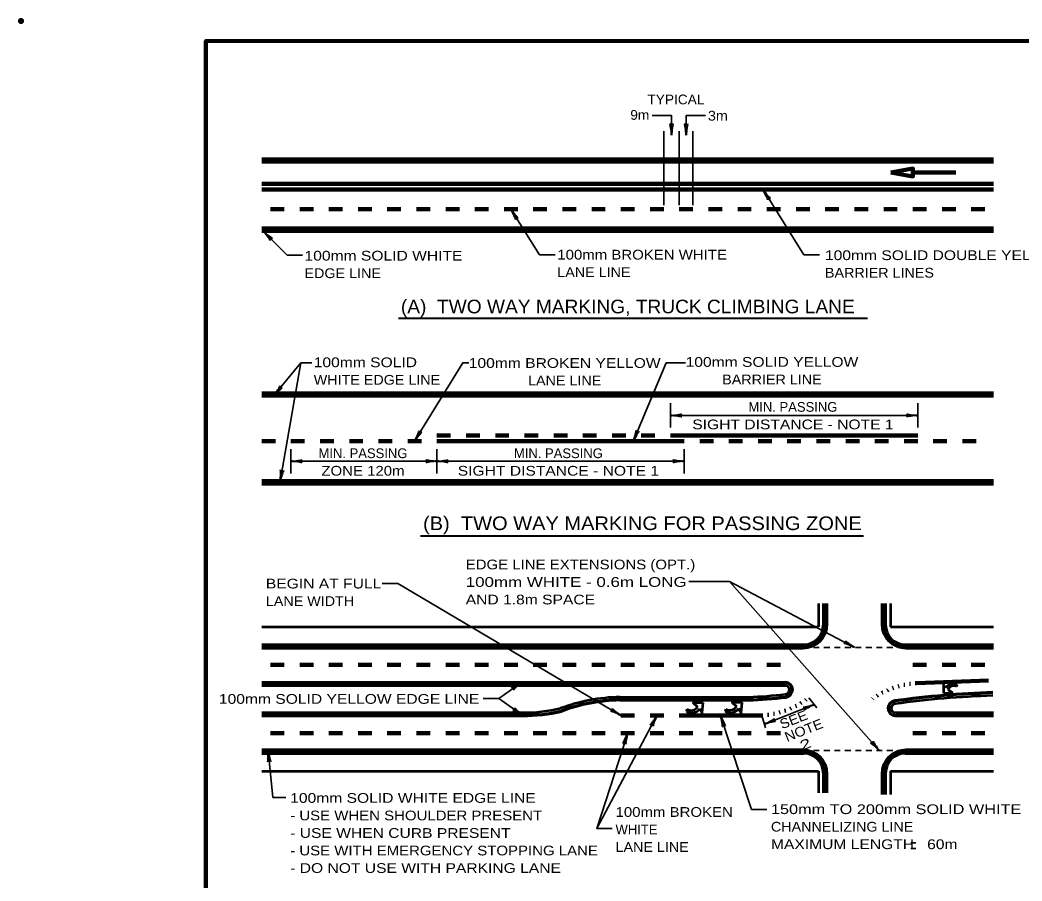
# Model space of a CAD drawing. Extents: x -90 to 765, y -1136 to -592.
# Drawn here: x -90.2 to 218.6, y -857.1 to -591.7 of the extents above; entities that cross this region are included whole.
import ezdxf
from ezdxf.enums import TextEntityAlignment as Align

# ---------------------------------------------------------------- set-up
doc = ezdxf.new("R2010")
doc.units = 0
doc.header["$LTSCALE"] = 1.2
doc.header["$PDMODE"] = 32
doc.header["$PDSIZE"] = 0.6
doc.linetypes.add('DOTTED', pattern=[1.5, 0.3, -1.2])
doc.linetypes.add('SHORT_DASHED', pattern=[2.7, 1.5, -1.2])
doc.layers.add('1', color=7, linetype='Continuous', lineweight=90)

msp = doc.modelspace()

# ---------------------------------------------------------------- linework, layer by layer
at = {"layer": '1', "lineweight": 35}
for p, q in [((108.194, -648.749), (108.194, -625.949)), ((112.994, -648.749), (112.994, -625.949)), ((117.194, -648.749), (117.194, -625.949)), ((-3.637, -697.37), (-0.31, -697.37)), ((110.294, -717.318), (110.294, -709.818)), ((186.494, -717.318), (186.494, -709.818)), ((110.294, -713.568), (186.494, -713.568)), ((-6.706, -723.918), (-6.706, -731.418)), ((38.294, -723.918), (38.294, -731.418)), ((114.494, -723.918), (114.494, -731.418)), ((115.938, -764.734), (128.515, -764.734)), ((57.322, -800.819), (64.765, -806.065)), ((139.244, -808.72), (154.603, -802.668)), ((152.905, -800.57), (155.395, -803.646)), ((125.716, -806.065), (135.211, -835.06)), ((138.438, -806.065), (139.594, -809.872)), ((-13.725, -816.856), (-12.315, -831.317)), ((-12.315, -831.317), (-8.296, -831.317)), ((135.211, -835.06), (140.011, -835.06)), ((87.549, -840.863), (92.28, -840.863))]:
    msp.add_line(p, q, dxfattribs=at)
at = {"layer": '1', "lineweight": 53}
for p, q in [((-15.706, -634.349), (209.894, -634.349)), ((-15.706, -656.849), (209.894, -656.849)), ((-15.706, -706.518), (209.894, -706.518)), ((-15.706, -734.718), (209.894, -734.718)), ((155.894, -771.565), (155.894, -778.765)), ((157.394, -771.565), (157.394, -778.165)), ((176.594, -771.565), (176.594, -778.165)), ((178.094, -771.565), (178.094, -778.765)), ((-15.706, -778.765), (155.894, -778.765)), ((178.094, -778.765), (209.894, -778.765)), ((-15.706, -784.165), (151.394, -784.165)), ((182.594, -784.165), (209.894, -784.165)), ((-15.706, -796.765), (145.715, -796.765)), ((198.567, -797.067), (198.645, -796.502)), ((94.694, -800.365), (134.294, -800.365)), ((-15.706, -805.165), (64.694, -805.165)), ((115.336, -804.126), (115.179, -804.772)), ((127.326, -804.056), (127.169, -804.702)), ((179.602, -805.165), (209.894, -805.165)), ((-15.706, -817.765), (151.394, -817.765)), ((182.594, -817.765), (209.894, -817.765)), ((-15.706, -823.165), (155.894, -823.165)), ((155.894, -823.165), (155.894, -829.868)), ((157.394, -823.765), (157.394, -829.868)), ((176.594, -823.765), (176.594, -830.365)), ((178.094, -823.165), (178.094, -830.365)), ((178.094, -823.165), (209.894, -823.165))]:
    msp.add_line(p, q, dxfattribs=at)
at = {"layer": '1'}
for p, q in [((-15.706, -635.249), (209.894, -635.249)), ((184.994, -638.699), (198.194, -638.699)), ((-15.706, -642.149), (209.894, -642.149)), ((-15.706, -643.949), (209.894, -643.949)), ((-13.006, -649.949), (-8.806, -649.949)), ((-4.006, -649.949), (0.194, -649.949)), ((4.994, -649.949), (9.194, -649.949)), ((13.994, -649.949), (18.194, -649.949)), ((22.994, -649.949), (27.194, -649.949)), ((31.994, -649.949), (36.194, -649.949)), ((40.994, -649.949), (45.194, -649.949)), ((49.994, -649.949), (54.194, -649.949)), ((58.994, -649.949), (63.194, -649.949)), ((67.994, -649.949), (72.194, -649.949)), ((76.994, -649.949), (81.194, -649.949)), ((85.994, -649.949), (90.194, -649.949)), ((94.994, -649.949), (99.194, -649.949)), ((103.994, -649.949), (108.194, -649.949)), ((112.994, -649.949), (117.194, -649.949)), ((121.994, -649.949), (126.194, -649.949)), ((130.994, -649.949), (135.194, -649.949)), ((139.994, -649.949), (144.194, -649.949)), ((148.994, -649.949), (153.194, -649.949)), ((157.994, -649.949), (162.194, -649.949)), ((166.994, -649.949), (171.194, -649.949)), ((175.994, -649.949), (180.194, -649.949)), ((184.994, -649.949), (189.194, -649.949)), ((193.994, -649.949), (198.194, -649.949)), ((202.994, -649.949), (207.194, -649.949)), ((-15.706, -655.949), (209.894, -655.949)), ((-15.706, -707.418), (209.894, -707.418)), ((-15.706, -721.518), (-11.506, -721.518)), ((-6.706, -721.518), (-2.506, -721.518)), ((2.294, -721.518), (6.494, -721.518)), ((11.294, -721.518), (15.494, -721.518)), ((20.294, -721.518), (24.494, -721.518)), ((29.294, -721.518), (33.494, -721.518)), ((38.294, -719.718), (42.494, -719.718)), ((38.294, -721.518), (114.494, -721.518)), ((47.294, -719.718), (51.494, -719.718)), ((56.294, -719.718), (60.494, -719.718)), ((65.294, -719.718), (69.494, -719.718)), ((74.294, -719.718), (78.494, -719.718)), ((83.294, -719.718), (87.494, -719.718)), ((92.294, -719.718), (96.494, -719.718)), ((101.294, -719.718), (105.494, -719.718)), ((110.294, -719.718), (186.494, -719.718)), ((119.294, -721.518), (123.494, -721.518)), ((128.294, -721.518), (132.494, -721.518)), ((137.294, -721.518), (141.494, -721.518)), ((146.294, -721.518), (150.494, -721.518)), ((155.294, -721.518), (159.494, -721.518)), ((164.294, -721.518), (168.494, -721.518)), ((173.294, -721.518), (177.494, -721.518)), ((182.294, -721.518), (186.494, -721.518)), ((191.294, -721.518), (195.494, -721.518)), ((200.294, -721.518), (204.494, -721.518)), ((-15.706, -733.818), (209.894, -733.818)), ((158.294, -771.565), (158.294, -777.865)), ((175.694, -771.565), (175.694, -777.865)), ((-15.706, -785.065), (151.094, -785.065)), ((182.894, -785.065), (209.894, -785.065)), ((-13.006, -790.465), (-8.806, -790.465)), ((-4.006, -790.465), (0.194, -790.465)), ((4.994, -790.465), (9.194, -790.465)), ((13.994, -790.465), (18.194, -790.465)), ((22.994, -790.465), (27.194, -790.465)), ((31.994, -790.465), (36.194, -790.465)), ((40.994, -790.465), (45.194, -790.465)), ((49.994, -790.465), (54.194, -790.465)), ((58.994, -790.465), (63.194, -790.465)), ((67.994, -790.465), (72.194, -790.465)), ((76.994, -790.465), (81.194, -790.465)), ((85.994, -790.465), (90.194, -790.465)), ((94.994, -790.465), (99.194, -790.465)), ((103.994, -790.465), (108.194, -790.465)), ((112.994, -790.465), (117.194, -790.465)), ((121.994, -790.465), (126.194, -790.465)), ((130.994, -790.465), (135.194, -790.465)), ((139.994, -790.465), (144.194, -790.465)), ((184.994, -790.465), (189.194, -790.465)), ((193.994, -790.465), (198.194, -790.465)), ((202.994, -790.465), (207.194, -790.465)), ((186.095, -796.077), (208.345, -795.288)), ((94.994, -806.065), (99.194, -806.065)), ((103.994, -806.065), (108.194, -806.065)), ((112.994, -806.065), (138.438, -806.065)), ((-13.006, -811.465), (-8.806, -811.465)), ((-4.006, -811.465), (0.194, -811.465)), ((4.994, -811.465), (9.194, -811.465)), ((13.994, -811.465), (18.194, -811.465)), ((22.994, -811.465), (27.194, -811.465)), ((31.994, -811.465), (36.194, -811.465)), ((40.994, -811.465), (45.194, -811.465)), ((49.994, -811.465), (54.194, -811.465)), ((58.994, -811.465), (63.194, -811.465)), ((67.994, -811.465), (72.194, -811.465)), ((76.994, -811.465), (81.194, -811.465)), ((85.994, -811.465), (90.194, -811.465)), ((94.994, -811.465), (99.194, -811.465)), ((103.994, -811.465), (108.194, -811.465)), ((112.994, -811.465), (117.194, -811.465)), ((121.994, -811.465), (126.194, -811.465)), ((130.994, -811.465), (135.194, -811.465)), ((139.994, -811.465), (144.194, -811.465)), ((184.994, -811.465), (189.194, -811.465)), ((193.994, -811.465), (198.194, -811.465)), ((202.994, -811.465), (207.194, -811.465)), ((-15.706, -816.865), (151.094, -816.865)), ((182.894, -816.865), (209.894, -816.865)), ((158.294, -824.065), (158.294, -829.868)), ((175.694, -824.065), (175.694, -830.365))]:
    msp.add_line(p, q, dxfattribs=at)
at = {"layer": '1', "lineweight": 40}
for p, q in [((26.444, -683.56), (171.056, -683.56)), ((33.209, -750.71), (169.778, -750.71))]:
    msp.add_line(p, q, dxfattribs=at)
at = {"layer": '1', "linetype": 'SHORT_DASHED', "lineweight": 35}
for p, q in [((151.094, -785.065), (182.894, -785.065)), ((151.094, -816.865), (182.894, -816.865))]:
    msp.add_line(p, q, dxfattribs=at)
at = {"layer": '1', "lineweight": 70}
for p, q in [((-15.706, -795.865), (145.715, -795.865)), ((94.694, -801.265), (134.294, -801.265)), ((-15.706, -806.065), (64.694, -806.065)), ((179.526, -806.065), (209.894, -806.065))]:
    msp.add_line(p, q, dxfattribs=at)
at = {"layer": '1', "lineweight": 158}
msp.add_lwpolyline([(758.78, -598.088), (-32.92, -598.188), (-32.82, -1124.188)], dxfattribs=at)
at = {"layer": '1', "lineweight": 35}
for points in [[(110.594, -627.149), (110.594, -621.149), (104.594, -621.149)], [(115.094, -627.149), (115.094, -621.149), (121.094, -621.149)], [(138.839, -643.949), (151.406, -664.013), (156.206, -664.013)], [(61.094, -649.949), (69.925, -664.049), (74.725, -664.049)], [(-15.186, -656.849), (-7.912, -664.122), (-3.112, -664.122)], [(-10.047, -733.818), (-3.637, -697.37), (-11.95, -707.418)], [(31.394, -721.518), (46.236, -697.37), (48.163, -697.37)], [(98.789, -721.548), (108.937, -697.37), (114.937, -697.37)], [(-6.706, -727.668), (38.294, -727.668), (114.494, -727.668)], [(21.442, -765.347), (26.242, -765.347), (94.994, -806.065)], [(166.994, -785.065), (128.515, -764.734), (174.648, -816.865)], [(52.522, -800.819), (57.322, -800.819), (64.35, -795.865)], [(97.094, -811.465), (87.549, -840.863), (106.094, -806.065)]]:
    msp.add_lwpolyline(points, dxfattribs=at)
at = {"layer": '1'}
msp.add_lwpolyline([(178.188, -638.699), (184.994, -639.899), (184.994, -637.499)], close=True, dxfattribs=at)
at = {"layer": '1', "lineweight": 53}
for points in [[(195.206, -797.524), (194.434, -796.51), (194.454, -799.202)], [(194.454, -799.202), (197.067, -798.93), (195.82, -798.032)], [(120.361, -802.132), (117.297, -802.141), (118.637, -803.33)], [(119.29, -803.991), (120.066, -805.258), (120.361, -802.132)], [(132.351, -802.062), (129.287, -802.071), (130.627, -803.26)], [(131.28, -803.921), (132.056, -805.188), (132.351, -802.062)]]:
    msp.add_lwpolyline(points, dxfattribs=at)
at = {"layer": '1'}
for centre, start, end in [((151.094, -777.865), 270, 0), ((182.894, -777.865), 180, 270), ((151.094, -824.065), 0, 90), ((182.894, -824.065), 90, 180)]:
    msp.add_arc(centre, 7.2, start, end, dxfattribs=at)
at = {"layer": '1', "lineweight": 53}
for centre, radius, start, end in [((151.394, -778.165), 6, 270, 0), ((182.594, -778.165), 6, 180, 270), ((145.611, -798.115), 1.352, 275.50285, 87.34859), ((197.447, -798.766), 2.561, 62.10089, 151.0021), ((130.168, -675.226), 125.207, 271.88819, 277.13284), ((219.529, -1094.063), 294.329, 91.91621, 97.80945), ((197.672, -798.912), 2.051, 64.13204, 154.56308), ((95.96, -857.195), 56.845, 91.29696, 110.144), ((179.63, -803.815), 1.352, 95.50285, 267.34859), ((65.107, -757.214), 47.953, 269.51539, 283.72008), ((116.836, -802.287), 2.987, 236.30972, 325.21093), ((116.592, -802.09), 2.392, 238.34087, 328.77191), ((128.826, -802.217), 2.987, 236.30972, 325.21093), ((128.582, -802.02), 2.392, 238.34087, 328.77191), ((151.394, -823.765), 6, 0, 90), ((182.594, -823.765), 6, 90, 180)]:
    msp.add_arc(centre, radius, start, end, dxfattribs=at)
at = {"layer": '1', "lineweight": 70}
for centre, radius, start, end in [((145.611, -798.115), 2.252, 275.50285, 87.34859), ((219.529, -1094.063), 295.229, 91.91621, 97.80945), ((95.96, -857.195), 55.945, 91.29696, 110.144), ((130.168, -675.226), 126.107, 271.88819, 277.13284), ((179.63, -803.815), 2.252, 95.50285, 267.34859), ((65.107, -757.214), 48.853, 269.51539, 283.72008)]:
    msp.add_arc(centre, radius, start, end, dxfattribs=at)
at = {"layer": '1', "linetype": 'DOTTED'}
for centre, start, end in [((187.821, -822.415), 93.75019, 125.33349), ((136.711, -779.727), 273.75019, 307.84593)]:
    msp.add_arc(centre, 26.394, start, end, dxfattribs=at)
at = {"layer": '1', "lineweight": 40}
for centre, major_axis, ratio, start_param, end_param in [((110.262, -625.84), (0.187, -2.143), 0.122415, 0.8963533, 3.1415927), ((110.262, -625.84), (0.187, -2.143), 0.122415, 0.8963533, 3.1415927), ((110.848, -625.804), (-0.211, -2.108), 0.07063, 3.1407148, 5.41811), ((110.848, -625.804), (-0.211, -2.108), 0.07063, 3.1407148, 5.41811), ((114.762, -625.84), (0.187, -2.143), 0.122415, 0.8963533, 3.1415927), ((115.348, -625.804), (-0.211, -2.108), 0.07063, 3.1407148, 5.41811), ((139.337, -645.223), (-0.94, 1.898), 0.07063, 3.1407148, 5.41811), ((139.815, -644.883), (-1.296, 1.717), 0.122415, 0.8963533, 3.1415927), ((61.592, -651.223), (-0.94, 1.898), 0.07063, 3.1407148, 5.41811), ((62.07, -650.883), (-1.296, 1.717), 0.122415, 0.8963533, 3.1415927), ((-14.414, -657.979), (-1.341, 1.639), 0.07063, 3.1407148, 5.41811), ((-14.025, -657.54), (-1.648, 1.383), 0.122415, 0.8963533, 3.1415927), ((-11.371, -706.198), (-1.222, -1.77), 0.122415, 0.8963533, 3.1415927), ((-11.371, -706.198), (-1.222, -1.77), 0.122415, 0.8963533, 3.1415927), ((-10.897, -706.544), (-1.506, -1.49), 0.07063, 3.1407148, 5.41811), ((-10.897, -706.544), (-1.506, -1.49), 0.07063, 3.1407148, 5.41811), ((111.603, -713.237), (-2.143, -0.187), 0.122415, 0.8963533, 3.1415927), ((111.603, -713.237), (-2.143, -0.187), 0.122415, 0.8963533, 3.1415927), ((185.149, -713.314), (2.108, -0.211), 0.07063, 3.1407148, 5.41811), ((185.149, -713.314), (2.108, -0.211), 0.07063, 3.1407148, 5.41811), ((111.638, -713.822), (-2.108, 0.211), 0.07063, 3.1407148, 5.41811), ((111.638, -713.822), (-2.108, 0.211), 0.07063, 3.1407148, 5.41811), ((185.184, -713.9), (2.143, 0.187), 0.122415, 0.8963533, 3.1415927), ((185.184, -713.9), (2.143, 0.187), 0.122415, 0.8963533, 3.1415927), ((31.797, -720.229), (-0.962, -1.924), 0.122415, 0.8963533, 3.1415927), ((31.797, -720.229), (-0.962, -1.924), 0.122415, 0.8963533, 3.1415927), ((32.314, -720.506), (-1.283, -1.685), 0.07063, 3.1407148, 5.41811), ((32.314, -720.506), (-1.283, -1.685), 0.07063, 3.1407148, 5.41811), ((98.99, -720.212), (-0.657, -2.048), 0.122415, 0.8963533, 3.1415927), ((99.544, -720.406), (-1.01, -1.862), 0.07063, 3.1407148, 5.41811), ((-5.362, -727.922), (-2.108, 0.211), 0.07063, 3.1407148, 5.41811), ((-5.362, -727.922), (-2.108, 0.211), 0.07063, 3.1407148, 5.41811), ((-5.397, -727.337), (-2.143, -0.187), 0.122415, 0.8963533, 3.1415927), ((-5.397, -727.337), (-2.143, -0.187), 0.122415, 0.8963533, 3.1415927), ((36.984, -728), (2.143, 0.187), 0.122415, 0.8963533, 3.1415927), ((36.949, -727.414), (2.108, -0.211), 0.07063, 3.1407148, 5.41811), ((39.638, -727.922), (-2.108, 0.211), 0.07063, 3.1407148, 5.41811), ((39.638, -727.922), (-2.108, 0.211), 0.07063, 3.1407148, 5.41811), ((39.603, -727.337), (-2.143, -0.187), 0.122415, 0.8963533, 3.1415927), ((39.603, -727.337), (-2.143, -0.187), 0.122415, 0.8963533, 3.1415927), ((113.184, -728), (2.143, 0.187), 0.122415, 0.8963533, 3.1415927), ((113.184, -728), (2.143, 0.187), 0.122415, 0.8963533, 3.1415927), ((113.149, -727.414), (2.108, -0.211), 0.07063, 3.1407148, 5.41811), ((113.149, -727.414), (2.108, -0.211), 0.07063, 3.1407148, 5.41811), ((-10.147, -732.471), (-0.187, -2.143), 0.122415, 0.8963533, 3.1415927), ((-10.147, -732.471), (-0.187, -2.143), 0.122415, 0.8963533, 3.1415927), ((-9.564, -732.538), (-0.573, -2.039), 0.07063, 3.1407148, 5.41811), ((-9.564, -732.538), (-0.573, -2.039), 0.07063, 3.1407148, 5.41811), ((165.681, -784.746), (1.982, -0.835), 0.122415, 0.8963533, 3.1415927), ((165.924, -784.212), (1.765, -1.171), 0.07063, 3.1407148, 5.41811), ((63.105, -796.432), (1.844, 1.042), 0.07063, 3.1407148, 5.41811), ((63.105, -796.432), (1.844, 1.042), 0.07063, 3.1407148, 5.41811), ((63.471, -796.89), (1.643, 1.388), 0.122415, 0.8963533, 3.1415927), ((63.471, -796.89), (1.643, 1.388), 0.122415, 0.8963533, 3.1415927), ((153.259, -802.925), (2.038, 0.577), 0.07063, 3.1407148, 5.41811), ((153.507, -803.456), (1.925, 0.96), 0.122415, 0.8963533, 3.1415927), ((63.504, -805.581), (1.859, -1.081), 0.122415, 0.8963533, 3.1415927), ((63.812, -805.083), (1.601, -1.387), 0.07063, 3.1407148, 5.41811), ((93.698, -805.683), (1.939, -0.931), 0.122415, 0.8963533, 3.1415927), ((93.966, -805.161), (1.706, -1.255), 0.07063, 3.1407148, 5.41811), ((105.237, -807.132), (1.177, 1.761), 0.07063, 3.1407148, 5.41811), ((105.237, -807.132), (1.177, 1.761), 0.07063, 3.1407148, 5.41811), ((105.771, -807.376), (0.842, 1.979), 0.122415, 0.8963533, 3.1415927), ((105.771, -807.376), (0.842, 1.979), 0.122415, 0.8963533, 3.1415927), ((125.893, -807.422), (-0.456, 2.069), 0.07063, 3.1407148, 5.41811), ((125.893, -807.422), (-0.456, 2.069), 0.07063, 3.1407148, 5.41811), ((126.438, -807.206), (-0.845, 1.978), 0.122415, 0.8963533, 3.1415927), ((126.438, -807.206), (-0.845, 1.978), 0.122415, 0.8963533, 3.1415927), ((140.341, -807.932), (-1.925, -0.96), 0.122415, 0.8963533, 3.1415927), ((140.341, -807.932), (-1.925, -0.96), 0.122415, 0.8963533, 3.1415927), ((140.588, -808.464), (-2.038, -0.577), 0.07063, 3.1407148, 5.41811), ((140.588, -808.464), (-2.038, -0.577), 0.07063, 3.1407148, 5.41811), ((96.437, -812.665), (0.851, 1.94), 0.07063, 3.1407148, 5.41811), ((97.005, -812.813), (0.484, 2.096), 0.122415, 0.8963533, 3.1415927), ((173.532, -816.104), (1.56, -1.481), 0.122415, 0.8963533, 3.1415927), ((173.532, -816.104), (1.56, -1.481), 0.122415, 0.8963533, 3.1415927), ((173.947, -815.69), (1.239, -1.718), 0.07063, 3.1407148, 5.41811), ((173.947, -815.69), (1.239, -1.718), 0.07063, 3.1407148, 5.41811), ((-13.847, -818.219), (0.005, 2.118), 0.07063, 3.1407148, 5.41811), ((-13.268, -818.127), (-0.395, 2.115), 0.122415, 0.8963533, 3.1415927)]:
    msp.add_ellipse(centre, major_axis=major_axis, ratio=ratio, start_param=start_param, end_param=end_param, dxfattribs=at)
at = {"layer": '1'}
msp.add_point((-89.92, -591.988), dxfattribs=at)

# ---------------------------------------------------------------- texts
for s, height, width, p in [('TYPICAL', 3, 1.05, (103.175, -617.663)), ('9m', 3, 1.05, (97.888, -622.428)), ('3m', 3, 1.1, (121.821, -622.678)), ('100mm SOLID WHITE', 3, 1.2, (-2.53, -665.829)), ('100mm BROKEN WHITE', 3, 1.15, (75.39, -665.51)), ('100mm SOLID DOUBLE YELLOW', 3, 1.2, (157.894, -665.678)), ('EDGE LINE', 3, 1.1, (-2.53, -671.229)), ('LANE LINE', 3, 1.1, (75.39, -670.91)), ('BARRIER LINES', 3, 1.1, (157.894, -671.077)), ('(A)  TWO WAY MARKING, TRUCK CLIMBING LANE', 4.2, 1.05, (27.18, -682.089)), ('100mm SOLID', 3, 1.2, (0.311, -698.685)), ('WHITE EDGE LINE', 3, 1.1, (0.311, -704.085)), ('(B)  TWO WAY MARKING FOR PASSING ZONE', 4.2, 1.1, (34, -748.901)), ('EDGE LINE EXTENSIONS (OPT.)', 3, 1.15, (47.168, -761.006)), ('BEGIN AT FULL', 3, 1.2, (-14.446, -766.895)), ('100mm WHITE - 0.6m LONG', 3, 1.3, (47.168, -766.406)), ('AND 1.8m SPACE', 3, 1.2, (47.168, -771.806)), ('LANE WIDTH', 3, 1.1, (-14.446, -772.295)), ('100mm SOLID YELLOW EDGE LINE', 3, 1.2, (-28.925, -802.449)), ('100mm SOLID WHITE EDGE LINE', 3, 1.2, (-6.945, -832.971)), ('150mm TO 200mm SOLID WHITE', 3, 1.25, (141.246, -836.437)), ('- USE WHEN SHOULDER PRESENT', 3, 1.15, (-6.945, -838.371)), ('100mm BROKEN', 3, 1.15, (93.346, -837.294)), ('CHANNELIZING LINE', 3, 1.1, (141.246, -841.837)), ('- USE WHEN CURB PRESENT', 3, 1.2, (-6.945, -843.771)), ('- USE WITH EMERGENCY STOPPING LANE', 3, 1.15, (-6.945, -849.171)), ('LANE LINE', 3, 1.1, (93.346, -848.094)), ('MAXIMUM LENGTH   60m', 3, 1.2, (141.246, -847.237)), ('- DO NOT USE WITH PARKING LANE', 3, 1.2, (-6.945, -854.571))]:
    msp.add_text(s, height=height, dxfattribs=dict(at, width=width)).set_placement(p)
for s, height, width, p in [('100mm BROKEN YELLOW', 3, 1.2, (77.661, -698.909)), ('100mm SOLID YELLOW', 3, 1.2, (141.555, -698.58)), ('BARRIER LINE', 3, 1.1, (141.555, -703.98)), ('LANE LINE', 3, 1.1, (77.661, -704.308)), ('SIGHT DISTANCE - NOTE 1', 3, 1.2, (148.022, -717.829)), ('ZONE 120m', 3, 1.15, (15.487, -732.12)), ('SIGHT DISTANCE - NOTE 1', 3, 1.2, (75.73, -732.12)), ('=', 4.8, 0.55, (185.132, -848.489))]:
    msp.add_text(s, height=height, dxfattribs=dict(at, width=width)).set_placement(p, align=Align.CENTER)
for p in [(148.022, -712.429), (15.487, -726.72), (75.73, -726.72)]:
    msp.add_text('MIN. PASSING', height=3, dxfattribs=at).set_placement(p, align=Align.CENTER)
for s, width, p in [('SEE', 1.1, (144.669, -810.318)), ('NOTE', 1.1, (146.209, -814.226)), ('  2', 1.5, (147.749, -818.133))]:
    msp.add_text(s, height=3, rotation=21.508, dxfattribs=dict(at, width=width)).set_placement(p)
msp.add_text('WHITE', height=3, dxfattribs=at).set_placement((93.346, -842.694))

doc.saveas('drawing.dxf')
